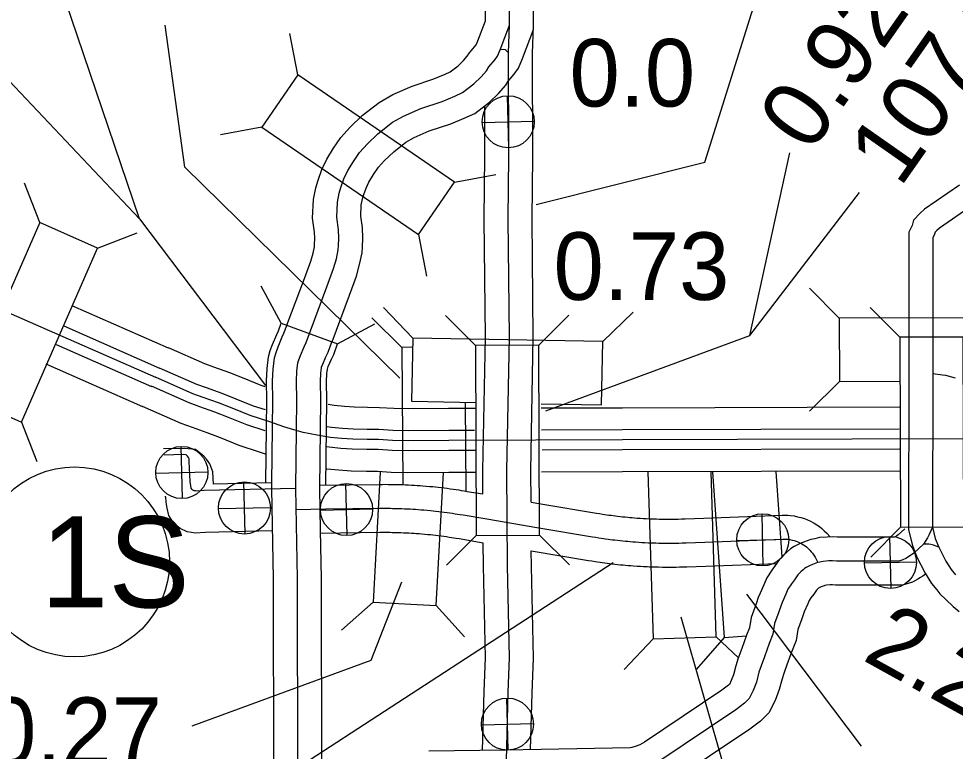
# Model space of a CAD drawing. Extents: x -83719 to 153526, y -11835 to 11446.
# Drawn here: x -69.2 to 126.1, y 533.4 to 686.1 of the extents above; entities that cross this region are included whole.
import ezdxf

# ---------------------------------------------------------------- set-up
doc = ezdxf.new("R2010")
doc.units = 0
for name, color, linetype in [('Level 10', 7, 'Continuous'), ('Level 19', 7, 'Continuous'), ('Level 20', 7, 'Continuous'), ('Level 21', 7, 'Continuous'), ('Level 25', 7, 'Continuous'), ('Level 26', 7, 'Continuous'), ('Level 27', 7, 'Continuous'), ('Level 58', 7, 'Continuous'), ('Level 59', 7, 'Continuous')]:
    doc.layers.add(name, color=color, linetype=linetype)

msp = doc.modelspace()

# ---------------------------------------------------------------- linework, layer by layer
at = {"layer": 'Level 10'}
for points in [[(-13.25, 622.18), (-9.6, 631.94), (-8.3, 635.5), (-7.82, 637.21), (-7.54, 638.49), (-7.53, 638.96), (-7.44, 640.34), (-7.5, 641.58), (-7.91, 644.47), (-7.71, 648.42), (-7.23, 650.84), (-6.78, 652.44), (-6, 654.61), (-4.97, 656.81), (-3.55, 659.08), (-2.04, 661.28), (-0.09, 663.47), (2.43, 665.87), (5.94, 668.64), (8.81, 670.26), (12.83, 672.01), (17.34, 673.52), (19.71, 674.54), (20.79, 675.01), (22.42, 676.27), (23.57, 677.39), (24.31, 678.24), (24.79, 678.99), (26.16, 680.65), (26.24, 680.76), (26.55, 681.48), (28.1, 685.65), (28.07, 692.02)], [(-3.86, 618.75), (-0.22, 628.47), (1.23, 632.44), (1.89, 634.82), (2.43, 637.29), (2.46, 638.49), (2.58, 640.25), (2.46, 642.55), (2.13, 644.92), (2.24, 647.19), (2.5, 648.52), (2.75, 649.4), (3.25, 650.78), (3.83, 652.01), (4.82, 653.6), (5.85, 655.1), (7.11, 656.51), (8.99, 658.31), (11.53, 660.31), (13.28, 661.3), (16.42, 662.67), (20.91, 664.17), (23.7, 665.37), (25.93, 666.35), (28.97, 668.7), (30.84, 670.51), (32.34, 672.23), (32.89, 673.09), (34.08, 674.54), (34.98, 675.79), (35.83, 677.75), (38.11, 683.86), (38.07, 692.05)], [(37.62, 585.31), (37.58, 591.81), (38.1, 619.67), (37.84, 644.32), (37.98, 657.42), (37.93, 678.87), (38.11, 684.6)], [(27.61, 587), (27.58, 591.87), (28.1, 619.71), (27.84, 644.32), (27.98, 657.47), (27.96, 667.72)], [(126.91, 651.39), (119.65, 646.35), (118.76, 645.55), (117.33, 644.07), (117.04, 642.94), (116.37, 641.6), (116.35, 638.81), (116.38, 612.06), (116.32, 579.52), (117.11, 576.23), (118.06, 573.86), (119.77, 570.5), (121.11, 568.37), (122.21, 567.03), (122.86, 566.21), (124.09, 565.02), (125.61, 563.57), (126.89, 562.51)], [(-16.4, 589.23), (-16.22, 606.56), (-16.28, 610.6), (-16.16, 613.04), (-15.88, 615.35), (-15.53, 616.51), (-15.12, 617.68), (-14.24, 619.74), (-13.87, 620.52), (-13.26, 622.15)], [(-6.25, 579.46), (-6.41, 588.16), (-6.22, 606.58), (-6.28, 610.43), (-6.19, 612.19), (-6.06, 613.3), (-6.02, 613.41), (-5.79, 614.05), (-5.13, 615.62), (-4.66, 616.59), (-3.87, 618.72)], [(-16.54, 589.29), (-28.56, 589.02), (-28.61, 590.32), (-28.71, 591.6), (-29.3, 593.28), (-30.04, 594.25), (-30.58, 594.9), (-32.31, 596.24), (-34.58, 596.49), (-38.97, 596.39)], [(-13.23, 491.01), (-16.09, 491.59), (-16, 528.62), (-16.07, 569.3), (-16.41, 588.12), (-16.4, 589.23)], [(-6.43, 588.86), (6.01, 589.01), (6.66, 589.01), (7.25, 589.02), (7.82, 589.01), (8.38, 589.01), (8.83, 589), (9.46, 588.99), (10.16, 588.97), (10.87, 588.95), (11.48, 588.93), (12.09, 588.9), (12.68, 588.87), (13.31, 588.83), (13.9, 588.79), (14.49, 588.75), (15.09, 588.71), (15.73, 588.65), (16.43, 588.59), (17.13, 588.53), (17.73, 588.46), (18.26, 588.41), (18.97, 588.33), (19.53, 588.26), (20.15, 588.18), (20.78, 588.1), (21.43, 588.01), (22.02, 587.92), (22.58, 587.83), (23.09, 587.75), (23.67, 587.66), (24.29, 587.55), (27.61, 587)], [(-16.37, 579.29), (-30.23, 578.98), (-32.36, 578.81), (-33.17, 578.98), (-34.02, 579.08), (-35.5, 579.8), (-36.76, 580.78), (-37.89, 582.52), (-38.21, 584.02), (-38.43, 585.32), (-38.47, 586.4), (-38.73, 586.39)], [(37.62, 585.31), (39.67, 584.96), (51.26, 583.01), (51.92, 582.9), (52.49, 582.81), (52.97, 582.74), (53.44, 582.67), (53.86, 582.61), (54.34, 582.55), (54.76, 582.49), (55.2, 582.44), (55.68, 582.38), (56.2, 582.32), (56.71, 582.26), (57.27, 582.21), (57.78, 582.16), (58.22, 582.11), (58.73, 582.07), (59.21, 582.03), (59.73, 581.99), (60.39, 581.95), (61, 581.91), (61.61, 581.87), (62.3, 581.84), (62.68, 581.83), (63.25, 581.8), (63.8, 581.79), (64.33, 581.77), (65.14, 581.76), (65.98, 581.75), (66.59, 581.75), (67.12, 581.76), (67.69, 581.76), (68.32, 581.78), (68.98, 581.79), (69.45, 581.81), (69.75, 581.82), (73.67, 581.97), (89.99, 582.59), (90.56, 582.6), (91.17, 582.58), (91.74, 582.53), (92.44, 582.44), (93.19, 582.27), (93.87, 582.11), (94.6, 581.87), (95.22, 581.62), (95.91, 581.3), (96.64, 580.9), (97.18, 580.56), (97.72, 580.19), (98.22, 579.78), (98.74, 579.34), (99.29, 578.81), (99.97, 578.05)], [(-6.2, 469.88), (-5.65, 473.25), (-4.75, 480.21), (-1.92, 498.91), (-6.07, 499.75), (-6, 528.62), (-6.07, 569.4), (-6.25, 579.46)], [(-6.24, 578.86), (6.11, 579.01), (6.72, 579.01), (7.24, 579.02), (7.76, 579.01), (8.26, 579.01), (8.67, 579), (9.23, 578.99), (9.87, 578.98), (10.51, 578.96), (11.05, 578.93), (11.6, 578.91), (12.14, 578.88), (12.7, 578.85), (13.23, 578.82), (13.77, 578.78), (14.3, 578.74), (14.88, 578.69), (15.51, 578.63), (16.14, 578.57), (16.69, 578.52), (17.16, 578.47), (17.8, 578.39), (18.3, 578.33), (18.86, 578.26), (19.43, 578.19), (20.02, 578.11), (20.54, 578.03), (21.05, 577.95), (21.51, 577.88), (22.04, 577.79), (22.63, 577.69), (27.68, 576.84)], [(115.51, 579.72), (114.16, 578.48), (113.9, 578.31), (113.39, 577.99), (113.36, 577.98), (101.46, 578.02), (100.51, 578.08), (99.36, 578.02), (97.77, 577.9), (96.76, 577.68), (95.94, 577.5), (94.4, 576.95), (93.47, 576.54), (92.49, 576.03), (91.72, 575.54), (90.99, 574.95), (90.32, 574.3), (89.37, 573.27), (88.53, 572.08), (87.81, 571.15), (86.75, 569.51), (86.14, 568.09), (85.38, 566.35), (85, 565.42), (84.54, 564.11), (83.53, 561.24), (83.17, 559.12), (82.57, 557.57), (81.56, 554.8), (80.82, 552.77), (80.33, 551.2), (79.84, 549.32), (79.37, 548.1), (78.96, 547.31), (78.8, 547.14), (77.41, 546.07), (61.24, 535.24), (60.32, 534.73), (59.31, 534.38), (58.65, 534.12), (58.26, 534.08), (32.33, 533.57), (16.34, 533.37)], [(27.53, 533.54), (27.83, 545.83), (28.12, 552.87), (27.71, 572), (27.68, 576.84)], [(37.54, 533.71), (37.83, 545.51), (38.13, 552.77), (37.64, 575.17)], [(37.64, 575.17), (49.62, 573.15), (50.33, 573.03), (50.97, 572.93), (51.5, 572.85), (52.01, 572.77), (52.48, 572.71), (53.01, 572.64), (53.49, 572.57), (53.98, 572.51), (54.51, 572.45), (55.08, 572.38), (55.65, 572.32), (56.27, 572.26), (56.83, 572.2), (57.33, 572.15), (57.89, 572.11), (58.43, 572.06), (59.01, 572.02), (59.73, 571.97), (60.41, 571.93), (61.1, 571.89), (61.85, 571.85), (62.29, 571.83), (62.92, 571.81), (63.52, 571.79), (64.12, 571.78), (65.01, 571.76), (65.94, 571.75), (66.62, 571.75), (67.21, 571.76), (67.85, 571.77), (68.55, 571.78), (69.27, 571.8), (69.79, 571.81), (70.12, 571.83), (74.05, 571.98), (88.85, 572.54)], [(119.86, 570.26), (119.26, 569.87), (118.79, 569.58), (118.26, 569.23), (117.12, 568.64), (116.44, 568.4), (115.03, 568), (113.53, 567.98), (101.1, 568.02), (100.46, 568.06), (100, 568.04), (99.2, 567.98), (98.88, 567.91), (98.71, 567.87), (98.13, 567.66), (97.8, 567.52), (97.57, 567.4), (97.46, 567.29), (97.16, 566.97), (96.57, 566.13), (95.98, 565.38), (95.61, 564.79), (95.32, 564.12), (94.59, 562.44), (94.34, 561.83), (93.97, 560.78), (93.25, 558.75), (92.87, 556.46), (91.93, 554.04), (90.95, 551.36), (90.29, 549.57), (89.95, 548.46), (89.37, 546.25), (88.5, 543.98), (87.16, 541.4), (85.48, 539.67), (83.25, 537.95), (66.45, 526.7)]]:
    msp.add_lwpolyline(points, dxfattribs=at)
at = {"layer": 'Level 19'}
for points in [[(-57.97, 626.23), (-37.98, 617.46)], [(-59.79, 622.03), (-39.82, 613.26)], [(-61.39, 618.18), (-41.49, 609.44)], [(-17.79, 609.36), (-18.63, 609.64), (-22.17, 611.05), (-25.18, 612.26), (-28.48, 613.42), (-30.37, 614.1), (-37.96, 617.45)], [(-63.5, 614.1), (-43.34, 605.25)], [(-17.73, 604.51), (-20.21, 605.34), (-23.87, 606.79), (-26.79, 607.97), (-30.01, 609.1), (-32.07, 609.84), (-39.81, 613.26)], [(-17.82, 600.14), (-21.65, 601.43), (-25.42, 602.93), (-28.26, 604.07), (-31.4, 605.17), (-33.62, 605.97), (-41.5, 609.45)], [(-17.76, 595.29), (-18.96, 595.69), (-23.22, 597.12), (-27.12, 598.67), (-29.88, 599.78), (-32.94, 600.85), (-35.32, 601.71), (-43.35, 605.25)], [(26.13, 604.84), (20.43, 604.82), (12.07, 604.76), (9.01, 604.84), (6.03, 604.99), (3.55, 605.02), (0.75, 605.07), (-1.29, 605.22), (-3.38, 605.42), (-4.66, 605.62)], [(114.45, 605.11), (56.67, 604.92), (39.74, 604.88)], [(25.86, 600.26), (20.46, 600.24), (12.03, 600.17), (8.83, 600.26), (5.88, 600.41), (3.48, 600.44), (0.55, 600.49), (-1.67, 600.65), (-3.95, 600.87), (-4.88, 601.02)], [(114.36, 600.52), (56.69, 600.34), (39.83, 600.29)], [(25.95, 596.09), (20.48, 596.07), (11.99, 596.01), (8.67, 596.09), (5.75, 596.24), (3.42, 596.27), (0.36, 596.33), (-2.02, 596.5), (-4.47, 596.74), (-4.95, 596.81)], [(114.45, 596.36), (56.7, 596.17), (39.92, 596.13)], [(25.95, 591.51), (20.5, 591.49), (11.95, 591.42), (8.49, 591.51), (5.6, 591.66), (3.35, 591.69), (0.16, 591.75), (-2.41, 591.93), (-4.96, 592.18)], [(114.54, 591.77), (56.71, 591.59), (39.83, 591.54)]]:
    msp.add_lwpolyline(points, dxfattribs=at)
at = {"layer": 'Level 20'}
for p, q in [((-11.02, 674.36), (-12.64, 683.01)), ((-18.48, 663.46), (-27.13, 661.85)), ((21.65, 651.98), (30.3, 653.6)), ((-64.79, 643.57), (-67.99, 651.77)), ((-52.71, 638.26), (-44.51, 641.46)), ((14.19, 641.09), (15.81, 632.44)), ((-14.43, 622.59), (-18.64, 630.32)), ((101.88, 623.68), (95.65, 629.89)), ((12.99, 619.51), (6.89, 625.85)), ((52.58, 618.77), (58.92, 624.88)), ((114.53, 619.67), (108.28, 625.88)), ((10.69, 617.57), (4.42, 623.75)), ((26.06, 617.97), (19.82, 624.18)), ((39.26, 618.01), (45.47, 624.25)), ((141.48, 623.72), (101.88, 623.68)), ((101.88, 623.68), (101.89, 610.48)), ((-14.43, 622.59), (-2.7, 618.28)), ((-2.7, 618.28), (5.03, 622.5)), ((12.99, 619.51), (12.74, 606.32)), ((52.58, 618.77), (12.99, 619.51)), ((12.78, 617.59), (10.69, 617.57)), ((10.69, 617.57), (10.91, 588.98)), ((52.34, 605.57), (52.58, 618.77)), ((101.89, 610.48), (95.67, 604.25)), ((101.89, 610.48), (114.63, 610.49)), ((12.74, 606.32), (26.03, 606.07)), ((24.12, 587.59), (23.98, 605.97)), ((39.73, 605.81), (52.34, 605.57)), ((-68.62, 602), (-65.42, 593.8)), ((114.65, 580.07), (108.45, 573.83)), ((26.17, 578.37), (19.97, 572.13)), ((39.37, 578.41), (45.61, 572.2)), ((4.7, 564.46), (-1.85, 558.58)), ((17.88, 563.75), (23.76, 557.2)), ((63.05, 556.8), (57.02, 550.38)), ((77.9, 557.11), (72.14, 550.46)), ((76.24, 557.21), (80.85, 552.87))]:
    msp.add_line(p, q, dxfattribs=at)
for points in [[(21.65, 651.98), (-11.02, 674.36), (-18.48, 663.46), (14.19, 641.09)], [(-68.62, 602), (-52.71, 638.26), (-64.79, 643.57), (-80.71, 607.31)], [(114.53, 619.67), (114.65, 580.07), (127.85, 580.12), (127.73, 619.72)], [(26.06, 617.97), (26.17, 578.37), (39.37, 578.41), (39.26, 618.01)]]:
    msp.add_lwpolyline(points, close=True, dxfattribs=at)
for points in [[(-17.65, 589.24), (-17.47, 606.56), (-17.53, 610.62), (-17.41, 613.15), (-17.11, 615.6), (-16.72, 616.89), (-16.29, 618.13), (-15.38, 620.26), (-15.02, 621.01), (-14.43, 622.59)], [(-5.16, 588.87), (-4.97, 606.59), (-5.03, 610.41), (-4.94, 612.09), (-4.83, 613.04), (-4.63, 613.6), (-3.99, 615.1), (-3.51, 616.1), (-2.7, 618.28)], [(6.16, 591.57), (4.7, 564.46), (17.88, 563.75), (19.37, 591.48)], [(61.96, 591.61), (63.05, 556.8), (76.24, 557.21), (75.16, 591.65)], [(75.46, 591.65), (77.9, 557.11), (82.52, 557.43)], [(89.95, 573.92), (88.69, 591.69)]]:
    msp.add_lwpolyline(points, dxfattribs=at)
at = {"layer": 'Level 21'}
msp.add_line((54.77, 572.65), (-106.85, 467.73), dxfattribs=at)
msp.add_lwpolyline([(38.71, 647.35), (73.86, 656.2), (90.3, 708.72)], dxfattribs=at)
at = {"layer": 'Level 26'}
for p, q in [((33, 659.16), (32.75, 670.01)), ((27.45, 664.46), (38.3, 664.71)), ((-35.04, 586.06), (-35.29, 596.91)), ((-40.59, 591.36), (-29.74, 591.61)), ((-21.99, 578.66), (-22.24, 589.51)), ((-0.71, 578.33), (-0.96, 589.17)), ((-27.54, 583.96), (-16.69, 584.21)), ((-6.26, 583.62), (4.59, 583.87)), ((86.04, 572.02), (85.79, 582.87)), ((112.67, 567.32), (112.42, 578.17)), ((80.49, 577.32), (91.34, 577.57)), ((107.12, 572.62), (117.97, 572.87)), ((32.84, 533.61), (32.59, 544.46)), ((27.29, 538.91), (38.14, 539.16))]:
    msp.add_line(p, q, dxfattribs=at)
for centre in [(32.87, 664.59), (-35.17, 591.48), (-22.11, 584.08), (-0.84, 583.75), (85.92, 577.44), (112.54, 572.74), (32.71, 539.03)]:
    msp.add_circle(centre, 5.43, dxfattribs=at)
at = {"layer": 'Level 27'}
msp.add_circle((-57.53, 572.85), 19.8, dxfattribs=at)
at = {"layer": 'Level 58'}
for p, q in [((-43.99, 644.33), (-59.45, 690.08)), ((83.25, 620.02), (91.57, 658.1)), ((82.57, 566.12), (106.44, 534.41)), ((68.88, 561.37), (82.57, 513.4))]:
    msp.add_line(p, q, dxfattribs=at)
for points in [[(10.27, 611.12), (-34.57, 655.1), (-38.61, 684.7)], [(-78.28, 680.66), (-43.99, 644.33), (-17.73, 609.64)], [(40.73, 604.33), (83.25, 620.02), (106.11, 649.87)], [(10.63, 568.65), (4.26, 552.26), (-33.05, 538.6)]]:
    msp.add_lwpolyline(points, dxfattribs=at)
at = {"layer": 'Level 59'}
for points in [[(-11, 528.62), (-11.07, 569.35), (-11.41, 588.14), (-11.22, 606.57), (-11.28, 610.51), (-11.18, 612.62), (-10.97, 614.32), (-10.78, 614.96), (-10.46, 615.87), (-9.69, 617.68), (-9.27, 618.56), (-4.91, 630.21), (-3.53, 633.97), (-2.96, 636.01), (-2.56, 637.89), (-2.54, 638.73), (-2.43, 640.3), (-2.52, 642.06), (-2.89, 644.7), (-2.74, 647.8), (-2.37, 649.68), (-2.02, 650.92), (-1.38, 652.7), (-0.57, 654.41), (0.63, 656.34), (1.9, 658.19), (3.51, 659.99), (5.71, 662.09), (8.74, 664.48), (11.05, 665.78), (14.62, 667.34), (19.13, 668.85), (21.71, 669.95), (23.36, 670.68), (25.7, 672.49), (27.21, 673.95), (28.32, 675.23), (28.84, 676.04), (30.12, 677.6), (30.61, 678.27), (31.19, 679.62), (33.11, 684.76), (33.07, 692.03)], [(32.42, 528.57), (32.83, 545.67), (33.12, 552.82), (32.71, 572.07), (32.58, 591.84), (33.1, 619.69), (32.84, 644.32), (32.98, 657.44), (32.93, 678.94), (33.11, 684.76)], [(32.93, 678.94), (32.29, 679.57), (31.85, 679.63), (31.19, 679.62)], [(129.75, 647.28), (122.77, 642.43), (122.24, 641.95), (121.85, 641.55), (121.75, 641.18), (121.36, 640.4), (121.35, 638.8), (121.38, 612.06), (121.32, 580.11), (121.89, 577.75), (122.61, 575.92), (124.12, 572.98), (125.18, 571.29), (126.1, 570.17)], [(-87.89, 632.09), (-40.66, 611.35)], [(128.54, 598.48), (56.69, 598.26), (20.47, 598.16), (12.01, 598.09), (8.75, 598.17), (5.82, 598.33), (3.45, 598.36), (0.45, 598.41), (-1.85, 598.57), (-4.21, 598.8), (-6.95, 599.23), (-9.85, 599.82), (-11.79, 600.39), (-13.87, 601.02), (-16.85, 602.01), (-20.93, 603.38), (-24.65, 604.86), (-27.53, 606.02), (-30.71, 607.14), (-32.85, 607.9), (-40.66, 611.35)], [(126.09, 611.17), (125.32, 611.32), (124.08, 611.7), (123.38, 611.79), (121.38, 612.06)], [(-11.41, 588.14), (-30.49, 587.71), (-32.05, 587.58), (-32.35, 587.65), (-32.58, 587.68), (-32.85, 587.81), (-33.02, 587.94), (-33.19, 588.2), (-33.3, 588.7), (-33.44, 589.57), (-33.61, 593.77), (-33.65, 594.3), (-33.75, 594.6), (-33.95, 594.87), (-34.09, 595.03), (-34.26, 595.16), (-34.79, 595.22), (-38.85, 595.12)], [(-11.4, 583.78), (-5.13, 583.87), (6.06, 584.01), (6.69, 584.01), (7.24, 584.02), (7.79, 584.01), (8.32, 584.01), (8.75, 584), (9.35, 583.99), (10.01, 583.97), (10.69, 583.95), (11.26, 583.93), (11.84, 583.9), (12.41, 583.87), (13.01, 583.84), (13.56, 583.8), (14.13, 583.76), (14.7, 583.72), (15.3, 583.67), (15.97, 583.61), (16.64, 583.55), (17.21, 583.49), (17.71, 583.44), (18.39, 583.36), (18.91, 583.3), (19.5, 583.22), (20.11, 583.14), (20.72, 583.06), (21.28, 582.97), (21.82, 582.89), (22.3, 582.82), (22.86, 582.73), (23.46, 582.62), (28.39, 581.79), (38.84, 580.03), (50.44, 578.08), (50.44, 578.08), (51.13, 577.97), (51.73, 577.87), (52.24, 577.79), (52.73, 577.72), (53.17, 577.66), (53.68, 577.59), (54.13, 577.53), (54.59, 577.47), (55.1, 577.41), (55.64, 577.35), (56.18, 577.29), (56.77, 577.23), (57.3, 577.18), (57.78, 577.13), (58.31, 577.09), (58.82, 577.05), (59.37, 577.01), (60.06, 576.96), (60.7, 576.92), (61.35, 576.88), (62.08, 576.85), (62.49, 576.83), (63.09, 576.81), (63.66, 576.79), (64.23, 576.78), (65.07, 576.76), (65.96, 576.75), (66.61, 576.75), (67.17, 576.76), (67.77, 576.76), (68.44, 576.78), (69.13, 576.8), (69.62, 576.81), (69.94, 576.82), (73.86, 576.97), (90.12, 577.59), (90.51, 577.6), (90.87, 577.59), (91.19, 577.56), (91.58, 577.51), (92.08, 577.4), (92.5, 577.3), (92.87, 577.17), (93.25, 577.02), (93.68, 576.83), (94.1, 576.6), (94.43, 576.38), (94.73, 576.18), (95.01, 575.95), (95.37, 575.63), (95.71, 575.32), (96.02, 574.97), (96.3, 574.63), (96.57, 574.23), (96.82, 573.84), (97.33, 572.83)], [(121.32, 580.11), (120.64, 578.56), (120.29, 577.86), (119.41, 576.51), (117.41, 574.67), (117.11, 574.43), (116.58, 574.09), (116.09, 573.78), (115.72, 573.55), (115.13, 573.24), (114.93, 573.17), (114.3, 572.99), (113.5, 572.98), (101.28, 573.02), (100.48, 573.07), (99.68, 573.03), (98.49, 572.94), (97.82, 572.8), (97.32, 572.69), (96.26, 572.3), (95.64, 572.03), (94.97, 571.68), (94.65, 571.48), (94.32, 571.21), (93.89, 570.8), (93.27, 570.12), (92.55, 569.11), (91.9, 568.26), (91.18, 567.15), (90.73, 566.11), (89.99, 564.39), (89.67, 563.62), (89.25, 562.45), (88.39, 560), (88.02, 557.79), (87.25, 555.8), (86.26, 553.08), (85.56, 551.17), (85.14, 549.83), (84.61, 547.78), (83.93, 546.04), (83.06, 544.35), (82.14, 543.41), (80.33, 542.01), (63.84, 530.97)], [(122.61, 575.92), (121.51, 576.34), (120.97, 576.47), (120.57, 576.53), (120.37, 576.52), (119.41, 576.51)]]:
    msp.add_lwpolyline(points, dxfattribs=at)

# ---------------------------------------------------------------- texts
at = {"layer": 'Level 25'}
for s, p in [('0.0', (45.65, 667.77)), ('0.27', (-75.96, 530.51))]:
    msp.add_text(s, height=14.08, dxfattribs=at).set_placement(p)
msp.add_text('2.22', height=14.08, rotation=331, dxfattribs=at).set_placement((106.41, 552.54))
at = {"layer": 'Level 27'}
msp.add_text('1S', height=19.008, dxfattribs=at).set_placement((-64.61, 563.34))
at = {"layer": 'Level 58'}
for s, p in [('107.01(U.P.)', (114.54, 650.65)), ('0.92(O.P.)', (95.81, 657.77))]:
    msp.add_text(s, height=14.08, rotation=55, dxfattribs=at).set_placement(p)
msp.add_text('0.73', height=14.08, dxfattribs=at).set_placement((42.31, 627.46))

doc.saveas('drawing.dxf')
